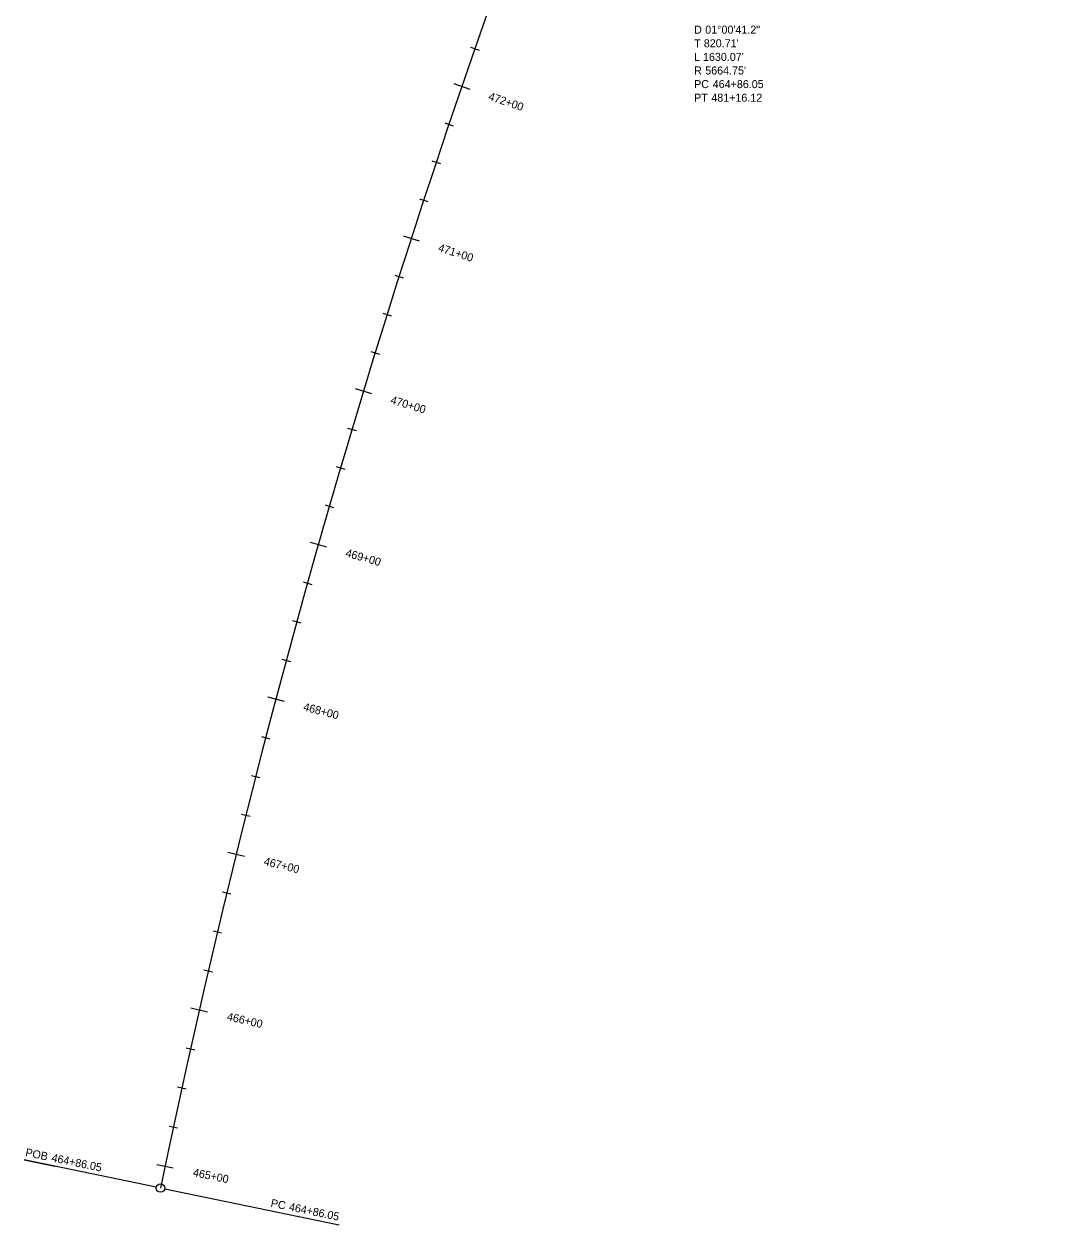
# Model space of a CAD drawing. Extents: x 2300830 to 2307917, y 756066 to 766359.
# Drawn here: x 2300830 to 2301469, y 756066 to 756817 of the extents above; entities that cross this region are included whole.
import ezdxf

# ---------------------------------------------------------------- set-up
doc = ezdxf.new("R2010")
doc.units = 0
for name, color, linetype in [('Draft_Curve Data Label', 7, 'Continuous'), ('Draft_Station Cardinal Lines', 7, 'Continuous'), ('Draft_Station Cardinal Points', 7, 'Continuous'), ('Draft_Station Labels Major', 7, 'Continuous'), ('Draft_Station Ticks Major', 7, 'Continuous'), ('Draft_Station Ticks Minor', 7, 'Continuous'), ('Geom_Baseline', 7, 'Continuous')]:
    doc.layers.add(name, color=color, linetype=linetype)

msp = doc.modelspace()

# ---------------------------------------------------------------- linework, layer by layer
at = {"layer": 'Draft_Station Cardinal Lines'}
msp.add_line((2300918.15, 756088.82), (2301027.17, 756066.29), dxfattribs=at)
at = {"layer": 'Draft_Station Cardinal Points'}
for p, q in [((2300912.92, 756089.9), (2300830.33, 756106.97)), ((2300830.33, 756106.97), (2300849.6, 756102.99)), ((2300915.53, 756089.36), (2300915.53, 756089.36)), ((2301027.17, 756066.29), (2301027.17, 756066.29))]:
    msp.add_line(p, q, dxfattribs=at)
msp.add_circle((2300915.53, 756089.36), 2.67, dxfattribs=at)
at = {"layer": 'Draft_Station Ticks Major'}
for p, q in [((2301098.6, 756779.32), (2301108.65, 756775.88)), ((2301067.02, 756684.34), (2301077.12, 756681.08)), ((2301037.12, 756588.82), (2301047.28, 756585.74)), ((2301008.91, 756492.79), (2301019.12, 756489.88)), ((2300982.4, 756396.27), (2300992.66, 756393.54)), ((2300957.6, 756299.3), (2300967.91, 756296.76)), ((2300934.51, 756201.9), (2300944.86, 756199.54)), ((2300913.15, 756104.12), (2300923.54, 756101.94))]:
    msp.add_line(p, q, dxfattribs=at)
at = {"layer": 'Draft_Station Ticks Minor'}
for p, q in [((2301109.19, 756802.13), (2301114.41, 756800.32)), ((2301092.99, 756754.81), (2301098.22, 756753.04)), ((2301085.05, 756731.09), (2301090.29, 756729.35)), ((2301077.21, 756707.34), (2301082.45, 756705.62)), ((2301061.84, 756659.73), (2301067.1, 756658.06)), ((2301054.32, 756635.88), (2301059.59, 756634.23)), ((2301046.9, 756611.99), (2301052.17, 756610.37)), ((2301032.38, 756564.12), (2301037.67, 756562.54)), ((2301025.28, 756540.14), (2301030.57, 756538.58)), ((2301018.28, 756516.12), (2301023.58, 756514.59)), ((2301004.61, 756468.01), (2301009.92, 756466.52)), ((2300997.93, 756443.9), (2301003.25, 756442.44)), ((2300991.36, 756419.77), (2300996.69, 756418.33)), ((2300978.53, 756371.42), (2300983.88, 756370.02)), ((2300972.28, 756347.2), (2300977.63, 756345.83)), ((2300966.14, 756322.95), (2300971.49, 756321.61)), ((2300954.17, 756274.38), (2300959.54, 756273.08)), ((2300948.35, 756250.05), (2300953.72, 756248.78)), ((2300942.63, 756225.7), (2300948.01, 756224.45)), ((2300931.52, 756176.93), (2300936.91, 756175.73)), ((2300926.13, 756152.5), (2300931.52, 756151.33)), ((2300920.85, 756128.06), (2300926.25, 756126.9))]:
    msp.add_line(p, q, dxfattribs=at)
at = {"layer": 'Geom_Baseline'}
msp.add_arc((2306463.05, 754942.84), 5664.75, 151.8357, 168.32293, dxfattribs=at)

# ---------------------------------------------------------------- texts
at = {"layer": 'Draft_Curve Data Label'}
for s, p in [('D ', (2301248.68, 756810.54)), ('01°00\'41.2"', (2301255.67, 756810.54)), ('T ', (2301248.68, 756802.04)), ("820.71'", (2301254.76, 756802.04)), ('L ', (2301248.68, 756793.54)), ("1630.07'", (2301254.25, 756793.54)), ('R ', (2301248.68, 756785.04)), ("5664.75'", (2301255.67, 756785.04)), ('PC ', (2301248.68, 756776.54)), ('464+86.05', (2301260.33, 756776.54)), ('PT ', (2301248.68, 756768.04)), ('481+16.12', (2301259.43, 756768.04))]:
    msp.add_text(s, height=5, dxfattribs=at).set_placement(p)
at = {"layer": 'Draft_Station Cardinal Points'}
for s, p in [('POB ', (2300830.83, 756109.4)), ('464+86.05', (2300847.18, 756106.02)), ('PC', (2300984.03, 756077.74)), ('464+86.05', (2300995.43, 756075.38))]:
    msp.add_text(s, height=5, rotation=348.32293, dxfattribs=at).set_placement(p)
at = {"layer": 'Draft_Station Labels Major'}
for s, rotation, p in [('472+00', 341.10169, (2301119.87, 756769.4)), ('471+00', 342.11314, (2301088.46, 756674.8)), ('470+00', 343.12458, (2301058.73, 756579.65)), ('469+00', 344.13602, (2301030.68, 756484)), ('468+00', 345.14747, (2301004.32, 756387.87)), ('467+00', 346.15891, (2300979.66, 756291.28)), ('466+00', 347.17035, (2300956.71, 756194.28)), ('465+00', 348.1818, (2300935.48, 756096.89))]:
    msp.add_text(s, height=5, rotation=rotation, dxfattribs=at).set_placement(p)

doc.saveas('drawing.dxf')
